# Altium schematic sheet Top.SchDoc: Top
size A4; Date: Not used; ApprovedBy: Not used; CheckedBy: Not used; Author: Not used; CompanyName: STMicroelectronics; DrawnBy: Not used; Engineer: Not used; Organization: Not used; Address1: Not used; Address2: Not used; Address3: Not used; Address4: Not used; DocumentNumber: 2; Revision: Not used; SheetNumber: 2; SheetTotal: 5
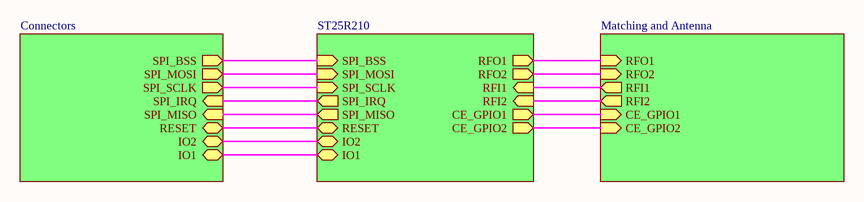
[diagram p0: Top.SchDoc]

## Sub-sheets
Connectors = Connectors.SchDoc: SPI_BSS (out), SPI_MOSI (out), SPI_SCLK (out), SPI_IRQ (in), SPI_MISO (in), RESET (bidir), IO2 (bidir), IO1 (bidir)
Matching and Antenna = Matching and Antenna.SchDoc: RFO1 (in), RFO2 (in), RFI1 (out), RFI2 (out), CE_GPIO2 (in), CE_GPIO1 (in)
ST25R210 = ST25R210.SchDoc: RFO1 (out), RFO2 (out), RFI1 (in), RFI2 (in), SPI_BSS (in), SPI_MOSI (in), SPI_SCLK (in), SPI_IRQ (out), SPI_MISO (out), RESET (bidir), IO1 (bidir), IO2 (bidir), CE_GPIO1 (out), CE_GPIO2 (out)

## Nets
(unnamed): sheet Connectors/SPI_BSS, sheet ST25R210/SPI_BSS
(unnamed): sheet Connectors/SPI_MOSI, sheet ST25R210/SPI_MOSI  [a separate net that carries the same name]
(unnamed): sheet Connectors/SPI_SCLK, sheet ST25R210/SPI_SCLK  [a separate net that carries the same name]
(unnamed): sheet Connectors/SPI_IRQ, sheet ST25R210/SPI_IRQ  [a separate net that carries the same name]
(unnamed): sheet Connectors/SPI_MISO, sheet ST25R210/SPI_MISO  [a separate net that carries the same name]
(unnamed): sheet Connectors/RESET, sheet ST25R210/RESET  [a separate net that carries the same name]
(unnamed): sheet Connectors/IO2, sheet ST25R210/IO2  [a separate net that carries the same name]
(unnamed): sheet Connectors/IO1, sheet ST25R210/IO1  [a separate net that carries the same name]
(unnamed): sheet Matching and Antenna/RFO1, sheet ST25R210/RFO1  [a separate net that carries the same name]
(unnamed): sheet Matching and Antenna/RFO2, sheet ST25R210/RFO2  [a separate net that carries the same name]
(unnamed): sheet Matching and Antenna/RFI1, sheet ST25R210/RFI1  [a separate net that carries the same name]
(unnamed): sheet Matching and Antenna/RFI2, sheet ST25R210/RFI2  [a separate net that carries the same name]
(unnamed): sheet Matching and Antenna/CE_GPIO2, sheet ST25R210/CE_GPIO2  [a separate net that carries the same name]
(unnamed): sheet Matching and Antenna/CE_GPIO1, sheet ST25R210/CE_GPIO1  [a separate net that carries the same name]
